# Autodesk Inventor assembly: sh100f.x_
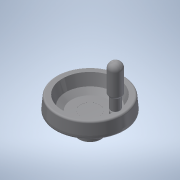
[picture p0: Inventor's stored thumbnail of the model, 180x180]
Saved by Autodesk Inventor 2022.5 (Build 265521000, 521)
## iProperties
Part Number: sh100f.x_
Material: 一般
Document SubType Name: Assembly
Designer: ImaoCorp
Sending System: SOLIDWORKS 2017-2017317
MC: AMD64
MC_MODEL: Intel64 Family 6 Model 60 Stepping 3, GenuineIntel
OS: Windows_NT
FRU: Parasolid Version 29.0, build 201,  4-17-2017
FORMAT: text
GUISE: transmit
KEY: sh100f
FILE: sh100f.x_t
DATE: Wed Sep 18 16:14:20 2019
Author: ImaoCorp
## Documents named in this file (3)
- X:\14_SW2022-Inv2022\00_全2023-1023新製品(TCC)まで\s\sh100f\SH100F.iam
- X:\14_SW2022-Inv2022\00_全2023-1023新製品(TCC)まで\s\sh100f\sh100f_01.ipt
- X:\14_SW2022-Inv2022\00_全2023-1023新製品(TCC)まで\s\sh100f\sh100f_02.ipt
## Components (2 placed, 2 different names)
1. sh100f_01
2. sh100f_02
